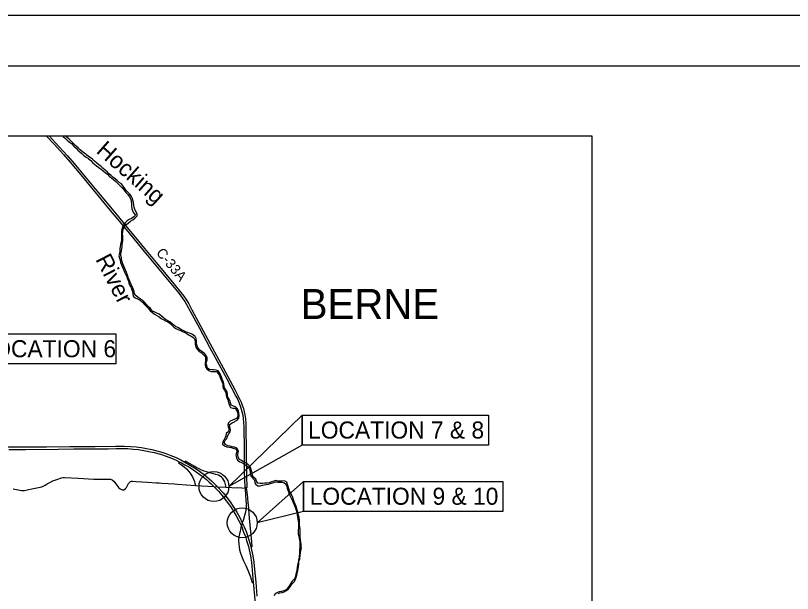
# Model space of a CAD drawing. Extents: x -51.9 to 34, y 0 to 23.3.
# Drawn here: x 6.91 to 14.66, y 16.24 to 22 of the extents above; entities that cross this region are included whole.
import ezdxf

# ---------------------------------------------------------------- set-up
doc = ezdxf.new("R2010")
doc.units = 0
for name, color, linetype in [('BR_P_Gen_Text', 7, 'Continuous'), ('Default', 7, 'Continuous'), ('GM_X_County_Road', 7, 'Continuous'), ('GM_X_County_Road_Text', 7, 'Continuous'), ('GM_X_Interchange_Ramps', 7, 'Continuous'), ('GM_X_Major_River', 7, 'Continuous'), ('GM_X_Major_River_Text', 7, 'Continuous'), ('GM_X_Township_Road', 7, 'Continuous'), ('GM_X_Township_Text', 7, 'Continuous'), ('GM_X_US_Route', 7, 'Continuous'), ('SH_Border', 7, 'Continuous'), ('SH_Cut_Line', 7, 'Continuous'), ('SH_Text', 7, 'Continuous')]:
    doc.layers.add(name, color=color, linetype=linetype)

msp = doc.modelspace()

# ---------------------------------------------------------------- linework, layer by layer
at = {"layer": 'BR_P_Gen_Text'}
for points in [[(6.5006, 18.827), (7.9094, 18.827), (7.9094, 18.5268), (6.5006, 18.5268)], [(9.7675, 18.0164), (9.7675, 17.7161), (9.0381, 17.3043)], [(9.7675, 18.0164), (11.6271, 18.0164), (11.6271, 17.7161), (9.7675, 17.7161)], [(9.7836, 17.3563), (9.7836, 17.056), (9.3204, 16.9434)], [(9.7836, 17.3563), (11.7711, 17.3563), (11.7711, 17.056), (9.7836, 17.056)]]:
    msp.add_lwpolyline(points, close=True, dxfattribs=at)
at = {"layer": 'Default'}
for centre in [(8.8891, 17.3043), (9.1714, 16.9434)]:
    msp.add_circle(centre, 0.149, dxfattribs=at)
at = {"layer": 'GM_X_County_Road'}
msp.add_line((9.2072, 17.2853), (9.1259, 17.2912), dxfattribs=at)
for points in [[(7.2165, 20.8014), (7.2937, 20.7181), (7.3887, 20.6148), (7.4551, 20.5389), (7.5602, 20.4136), (7.6838, 20.2636), (7.8384, 20.0776), (7.9796, 19.9067), (8.0908, 19.7728), (8.1642, 19.6842), (8.3391, 19.4732), (8.5374, 19.233), (8.5735, 19.1864), (8.5995, 19.1478), (8.6324, 19.0911), (8.7437, 18.8833), (8.8459, 18.6944), (8.9023, 18.5907), (9.0168, 18.378), (9.1078, 18.2071), (9.1262, 18.171), (9.141, 18.1359), (9.1548, 18.0984), (9.1688, 18.0528), (9.1764, 18.0146), (9.1819, 17.9788), (9.1851, 17.9474), (9.1869, 17.9004), (9.1894, 17.6782), (9.1909, 17.4499), (9.1967, 17.3), (9.2072, 17.2853)], [(7.2449, 20.8014), (7.3435, 20.6952), (7.4299, 20.601), (7.4952, 20.5238), (7.6044, 20.3929), (7.7527, 20.2143), (7.9056, 20.0299), (8.055, 19.8496), (8.1063, 19.7859), (8.1966, 19.6782), (8.3281, 19.5193), (8.4876, 19.3262), (8.5595, 19.2395), (8.5876, 19.204), (8.611, 19.169), (8.6373, 19.1259), (8.6691, 19.0673), (8.7584, 18.9008), (8.8526, 18.7271), (8.9162, 18.611), (9.0055, 18.4433), (9.0965, 18.2734), (9.1488, 18.1726), (9.1606, 18.146), (9.1716, 18.1148), (9.1829, 18.0812), (9.1907, 18.0492), (9.1971, 18.0211), (9.2028, 17.9781), (9.2069, 17.9333), (9.2083, 17.8659), (9.2115, 17.6888), (9.2124, 17.4033), (9.2173, 17.2984), (9.2072, 17.2853)], [(8.7051, 17.3164), (8.8891, 17.3043), (8.925, 17.3025), (9.0082, 17.2985), (9.1259, 17.2912)], [(8.7051, 17.3164), (8.8891, 17.3043), (8.925, 17.3025), (9.0082, 17.2985), (9.1259, 17.2912)]]:
    msp.add_lwpolyline(points, dxfattribs=at)
at = {"layer": 'GM_X_Interchange_Ramps'}
for points in [[(8.5419, 17.5519), (8.535, 17.5396), (8.5644, 17.5208), (8.591, 17.5003), (8.6162, 17.48), (8.6387, 17.4549), (8.6589, 17.4277), (8.6699, 17.4109)], [(9.0082, 17.2985), (9.0061, 17.3114), (8.9975, 17.3499), (8.9892, 17.3678), (8.9767, 17.3855), (8.9655, 17.397), (8.9516, 17.4086), (8.9351, 17.4187), (8.9091, 17.4262), (8.8374, 17.4453), (8.7928, 17.4586), (8.7639, 17.4693), (8.7408, 17.4797), (8.7194, 17.4925), (8.6916, 17.5092), (8.6057, 17.5564), (8.6001, 17.5491)], [(9.0082, 17.2985), (9.0061, 17.3114), (8.9975, 17.3499), (8.9892, 17.3678), (8.9767, 17.3855), (8.9655, 17.397), (8.9516, 17.4086), (8.9351, 17.4187), (8.9091, 17.4262), (8.8374, 17.4453), (8.7928, 17.4586), (8.7639, 17.4693), (8.7408, 17.4797), (8.7194, 17.4925), (8.6916, 17.5092), (8.6057, 17.5564), (8.6001, 17.5491)], [(8.6699, 17.4109), (8.6754, 17.4025), (8.6867, 17.3765), (8.6939, 17.356), (8.6986, 17.3357), (8.7051, 17.3164)], [(9.2072, 17.2853), (9.1989, 17.2752), (9.2083, 17.1733), (9.2109, 17.1288), (9.2095, 17.0923), (9.204, 17.0498), (9.1912, 17.0024), (9.1802, 16.9647), (9.1714, 16.9434), (9.1625, 16.9113), (9.1577, 16.895), (9.1502, 16.8569), (9.1438, 16.8341), (9.1383, 16.8032), (9.1357, 16.7676), (9.1372, 16.7309), (9.1395, 16.7034), (9.1444, 16.6736), (9.1537, 16.6404), (9.1629, 16.614), (9.1846, 16.5649), (9.2064, 16.5181), (9.2274, 16.4709), (9.2401, 16.4379), (9.2543, 16.4042), (9.2611, 16.3825), (9.2693, 16.3488), (9.282, 16.3528)], [(9.2326, 17.1263), (9.2318, 17.1354), (9.2266, 17.1949), (9.2156, 17.2765), (9.2072, 17.2853)], [(9.2572, 16.7055), (9.2711, 16.7068), (9.2636, 16.7895), (9.2537, 16.8873), (9.2451, 16.9885), (9.2326, 17.1263)]]:
    msp.add_lwpolyline(points, dxfattribs=at)
at = {"layer": 'GM_X_Major_River'}
for points in [[(7.3779, 20.8014), (7.3857, 20.7943), (7.407, 20.7744), (7.4243, 20.7584), (7.4476, 20.7385), (7.4669, 20.7239), (7.4922, 20.6993), (7.5149, 20.6787), (7.5329, 20.6581), (7.5515, 20.6422), (7.5728, 20.6236), (7.5908, 20.6063), (7.6154, 20.5877), (7.6367, 20.5738), (7.6387, 20.5704)], [(7.8369, 20.4254), (7.8258, 20.4371), (7.7805, 20.4782), (7.7632, 20.4935), (7.7399, 20.5114), (7.7212, 20.5274), (7.6986, 20.5473), (7.6773, 20.5679), (7.656, 20.5858), (7.6387, 20.5964), (7.618, 20.6124), (7.6007, 20.625), (7.5794, 20.6416), (7.5541, 20.6628), (7.5335, 20.6808), (7.5102, 20.7014), (7.4902, 20.722), (7.4682, 20.7446), (7.4449, 20.7692), (7.4209, 20.7877), (7.406, 20.8014)], [(7.6387, 20.5704), (7.6594, 20.5558), (7.6787, 20.5366), (7.7007, 20.516), (7.7173, 20.5014), (7.7399, 20.4854), (7.7626, 20.4675), (7.7846, 20.4509), (7.8079, 20.433), (7.8265, 20.4191), (7.8485, 20.3971), (7.8665, 20.3825), (7.8904, 20.3619), (7.9104, 20.346), (7.9337, 20.3234)], [(7.981, 19.8022), (7.9783, 19.8242), (7.9802, 19.8469), (7.9835, 19.8675), (7.9934, 19.8902), (8.0093, 19.913), (8.0325, 19.931), (8.057, 19.9491), (8.0802, 19.9645), (8.1047, 19.9819), (8.1226, 20.0027), (8.1245, 20.0213), (8.1118, 20.0433), (8.0998, 20.0659), (8.0938, 20.0892), (8.0911, 20.1112), (8.0883, 20.1346), (8.0816, 20.1579), (8.0776, 20.1745), (8.0656, 20.1965), (8.0522, 20.2151), (8.0336, 20.2351), (8.0143, 20.257), (7.9989, 20.2763), (7.9829, 20.2989), (7.9656, 20.3215), (7.9443, 20.3368), (7.9243, 20.3547), (7.903, 20.3733), (7.881, 20.3899), (7.8591, 20.4085), (7.8369, 20.4254)], [(7.9337, 20.3234), (7.9544, 20.3035), (7.9737, 20.2822), (7.991, 20.2609), (8.0117, 20.237), (8.0303, 20.2164), (8.047, 20.1938), (8.061, 20.1698), (8.0644, 20.1478), (8.0678, 20.1238), (8.0678, 20.0992), (8.0706, 20.0765), (8.0779, 20.0545), (8.09, 20.0312), (8.106, 20.01), (8.0901, 19.9926), (8.0669, 19.9758), (8.045, 19.9657), (8.0238, 19.9537), (8.0039, 19.9343), (7.988, 19.9116), (7.9781, 19.8909), (7.9695, 19.8675), (7.9676, 19.8508), (7.967, 19.8301), (7.9677, 19.8041), (7.9684, 19.7875), (7.9665, 19.7661), (7.9639, 19.7421), (7.9586, 19.7188), (7.9547, 19.6974), (7.9515, 19.6741), (7.9502, 19.6507), (7.9463, 19.6281), (7.9417, 19.6054), (7.9458, 19.5814), (7.9538, 19.5601), (7.9578, 19.5374), (7.9659, 19.5141), (7.9772, 19.4908), (7.9873, 19.4675), (7.9973, 19.4422), (8.0073, 19.4209), (8.0193, 19.3956), (8.0267, 19.375), (8.0354, 19.3517), (8.0401, 19.331), (8.0515, 19.3084), (8.0622, 19.2884), (8.0708, 19.2665), (8.0762, 19.2491), (8.0789, 19.2251), (8.0823, 19.2012), (8.103, 19.1859), (8.1262, 19.1766), (8.1535, 19.1621), (8.1748, 19.1435), (8.1941, 19.1235), (8.2148, 19.1009), (8.2348, 19.0797), (8.2541, 19.0571), (8.2754, 19.0411), (8.2967, 19.0239), (8.3193, 19.0093), (8.342, 18.9967), (8.3613, 18.9814), (8.3819, 18.9688), (8.4045, 18.9582), (8.4285, 18.9476), (8.4504, 18.9344), (8.4677, 18.9138), (8.4891, 18.8938), (8.5103, 18.8806), (8.533, 18.8713), (8.5549, 18.8614), (8.5769, 18.8508), (8.5981, 18.8389), (8.6214, 18.8256), (8.6421, 18.8143), (8.6627, 18.8037), (8.6893, 18.7878), (8.6987, 18.7659), (8.7034, 18.7445), (8.7028, 18.7199), (8.7101, 18.6952), (8.7202, 18.6739), (8.7415, 18.6513), (8.7634, 18.6367), (8.7848, 18.6188), (8.8034, 18.5962), (8.8061, 18.5755), (8.8042, 18.5575), (8.8023, 18.5355), (8.803, 18.5155), (8.8063, 18.4989), (8.817, 18.4769), (8.8383, 18.4603), (8.8603, 18.4517), (8.8829, 18.4498), (8.9028, 18.4512), (8.9148, 18.4512)], [(9.0928, 17.9512), (9.0995, 17.9558), (9.1214, 17.9659), (9.1386, 17.9846), (9.1392, 18.014), (9.1384, 18.038), (9.1331, 18.0566), (9.1237, 18.0799), (9.1057, 18.1005), (9.0831, 18.1051), (9.0618, 18.1157), (9.0531, 18.139), (9.0478, 18.1623), (9.0331, 18.1843), (9.0257, 18.2063), (9.025, 18.2249), (9.0216, 18.2483), (9.0063, 18.2695), (8.9949, 18.2902), (8.9896, 18.3081), (8.9862, 18.3301), (8.9821, 18.3521), (8.9708, 18.3748), (8.9667, 18.3921), (8.9587, 18.4107), (8.9487, 18.436), (8.9307, 18.4586), (8.9121, 18.4646), (8.8895, 18.4685), (8.8669, 18.4671), (8.8456, 18.4703), (8.825, 18.4863), (8.8176, 18.5109), (8.8129, 18.5289), (8.8135, 18.5462), (8.8201, 18.5689), (8.8227, 18.5896), (8.8127, 18.6102), (8.796, 18.6322), (8.7721, 18.6481), (8.7481, 18.6647), (8.7281, 18.6893), (8.7194, 18.7133), (8.716, 18.7359), (8.7159, 18.7586), (8.7126, 18.7792), (8.7012, 18.8005), (8.6766, 18.8198), (8.6546, 18.8297), (8.6314, 18.8376), (8.6094, 18.8462), (8.5881, 18.8562), (8.5668, 18.8667), (8.5469, 18.8787), (8.5296, 18.8886), (8.5063, 18.9005), (8.4717, 18.9258), (8.4484, 18.9464), (8.4271, 18.9583), (8.4045, 18.9715), (8.3832, 18.9888), (8.3639, 19.0061), (8.3412, 19.024), (8.3193, 19.0333), (8.3, 19.0419), (8.2774, 19.0545), (8.2554, 19.0784), (8.2327, 19.101), (8.2127, 19.1216), (8.1954, 19.1422), (8.1761, 19.1635), (8.1528, 19.1767), (8.1348, 19.188), (8.1149, 19.2053), (8.0969, 19.2272), (8.0948, 19.2505), (8.0828, 19.2752), (8.0721, 19.2985), (8.0641, 19.3178), (8.052, 19.3411), (8.0433, 19.367), (8.034, 19.3883), (8.0253, 19.4116), (8.0166, 19.4376), (8.0099, 19.4556), (8.0012, 19.4769), (7.9905, 19.5009), (7.9818, 19.5248), (7.9737, 19.5461), (7.9677, 19.5675), (7.9663, 19.5841), (7.9603, 19.6081), (7.9615, 19.6321), (7.9655, 19.6541), (7.9694, 19.6755), (7.972, 19.6975), (7.9733, 19.7142), (7.9779, 19.7375), (7.9791, 19.7542), (7.9811, 19.7795), (7.981, 19.8022)], [(8.9148, 18.4512), (8.9314, 18.4326), (8.9454, 18.4113), (8.9521, 18.39), (8.9575, 18.3734), (8.9682, 18.3514), (8.9762, 18.3301), (8.9776, 18.3061), (8.9823, 18.2835), (8.9963, 18.2608), (9.0077, 18.2402), (9.0117, 18.2196), (9.0158, 18.1969), (9.0285, 18.1736), (9.0325, 18.1563), (9.0392, 18.1323), (9.0446, 18.111), (9.0553, 18.091), (9.0759, 18.0858), (9.1004, 18.0852), (9.1131, 18.0646), (9.1225, 18.0413), (9.1259, 18.0219), (9.1259, 18.0039), (9.1187, 17.9872), (9.0988, 17.9752), (9.0749, 17.9664), (9.0517, 17.9564), (9.0318, 17.9356), (9.0265, 17.9189), (9.0299, 17.8983), (9.0393, 17.875), (9.0294, 17.8516), (9.0121, 17.8342), (9.0076, 17.8095), (9.0023, 17.7922), (8.9864, 17.7668), (8.9778, 17.7494), (8.9746, 17.7274), (8.9952, 17.7095), (9.0185, 17.7016), (9.0404, 17.6983), (9.0617, 17.6924), (9.0823, 17.6865), (9.1049, 17.6805), (9.1202, 17.6606), (9.113, 17.6392), (9.1084, 17.6165), (9.1131, 17.5912), (9.1245, 17.5686), (9.1464, 17.5507), (9.1637, 17.5434), (9.1877, 17.5301), (9.2316, 17.501), (9.2443, 17.4797), (9.2503, 17.4577), (9.2517, 17.4397), (9.2537, 17.423), (9.2571, 17.4064), (9.2931, 17.3665), (9.2985, 17.3432), (9.3058, 17.3252), (9.3265, 17.3126), (9.3497, 17.3127), (9.3729, 17.3188), (9.3915, 17.3215), (9.4115, 17.3242), (9.4314, 17.3283)], [(9.5489, 17.3567), (9.5276, 17.358), (9.5077, 17.3639), (9.4877, 17.3592), (9.4645, 17.3511), (9.4413, 17.343), (9.4181, 17.3383), (9.3961, 17.3382), (9.3729, 17.3348), (9.3497, 17.3334), (9.3264, 17.3366), (9.315, 17.3566), (9.3057, 17.3772), (9.2864, 17.3945), (9.2737, 17.4158), (9.269, 17.4411), (9.2649, 17.4611), (9.2582, 17.485), (9.2469, 17.5063), (9.2269, 17.5283), (9.2069, 17.5375), (9.1856, 17.5481), (9.163, 17.5627), (9.1424, 17.5753), (9.1297, 17.5973), (9.1277, 17.6199), (9.1309, 17.642), (9.1335, 17.6586), (9.1175, 17.687), (9.0949, 17.6958), (9.0723, 17.7018), (9.0504, 17.707), (9.0264, 17.7116), (9.0045, 17.7242), (8.9911, 17.7428), (9.0024, 17.7655), (9.0169, 17.7849), (9.0235, 17.8069), (9.0374, 17.8296), (9.0506, 17.8503), (9.0559, 17.8677), (9.0491, 17.901), (9.0458, 17.9223), (9.071, 17.9411), (9.0928, 17.9512)], [(9.5287, 16.2387), (9.5473, 16.2441), (9.5686, 16.2495), (9.5905, 16.2562), (9.613, 16.267), (9.6322, 16.2843), (9.6494, 16.3064), (9.6673, 16.3311), (9.6878, 16.3545), (9.7011, 16.3786), (9.7103, 16.4006), (9.7162, 16.4226), (9.7208, 16.4393), (9.7261, 16.464), (9.73, 16.4853), (9.7339, 16.508), (9.7352, 16.5293), (9.7371, 16.5534), (9.7407, 16.5684), (9.7454, 16.5842), (9.7482, 16.6187), (9.7535, 16.6421), (9.7574, 16.6634), (9.7613, 16.6888), (9.7606, 16.7061), (9.7592, 16.7294), (9.7571, 16.7507), (9.7538, 16.7727), (9.7497, 16.7954), (9.7483, 16.818), (9.7483, 16.838), (9.7482, 16.8774), (9.7468, 16.8994), (9.7434, 16.9234), (9.7433, 16.9474), (9.7419, 16.9707), (9.7379, 16.9973), (9.7331, 17.02), (9.7291, 17.038), (9.7237, 17.06), (9.7157, 17.0839), (9.7083, 17.1066), (9.7003, 17.1299), (9.6903, 17.1525), (9.6842, 17.1705), (9.6749, 17.1938), (9.6648, 17.2184), (9.6562, 17.2364), (9.6441, 17.259), (9.6348, 17.281), (9.6294, 17.3036), (9.6234, 17.3263), (9.6153, 17.3496), (9.5934, 17.3608), (9.5714, 17.3594), (9.5489, 17.3567)], [(9.4314, 17.3283), (9.4546, 17.3364), (9.4778, 17.3431), (9.5037, 17.3499), (9.527, 17.3479), (9.5496, 17.3467), (9.5675, 17.3468), (9.5854, 17.3441), (9.6054, 17.3275), (9.6174, 17.3063), (9.6208, 17.2883), (9.6275, 17.2683), (9.6329, 17.2516), (9.6376, 17.2337), (9.6503, 17.207), (9.6616, 17.1824), (9.6723, 17.1611), (9.683, 17.1365), (9.6924, 17.1145), (9.7024, 17.0905), (9.7084, 17.0692), (9.7145, 17.0453), (9.7185, 17.0239), (9.7266, 16.9786), (9.7293, 16.9606), (9.732, 16.94), (9.7328, 16.9153), (9.7322, 16.8933), (9.7296, 16.8713), (9.729, 16.8546), (9.7303, 16.8333), (9.7351, 16.8093), (9.7398, 16.7867), (9.7445, 16.7627), (9.7465, 16.74), (9.7466, 16.716), (9.7453, 16.6974), (9.7441, 16.6747), (9.7435, 16.654), (9.7422, 16.6314), (9.7403, 16.6134), (9.739, 16.5954), (9.7331, 16.5707), (9.7285, 16.5453), (9.7232, 16.5193), (9.72, 16.496), (9.7167, 16.4786), (9.7121, 16.4526), (9.7069, 16.4313), (9.701, 16.4092), (9.6911, 16.3859), (9.6699, 16.3598), (9.6533, 16.3357), (9.6414, 16.317), (9.6276, 16.2963), (9.6083, 16.2743), (9.5871, 16.2635), (9.5632, 16.2575), (9.5413, 16.2554), (9.5241, 16.2493), (9.5028, 16.2393), (9.4849, 16.2192)]]:
    msp.add_lwpolyline(points, dxfattribs=at)
at = {"layer": 'GM_X_Township_Road'}
for points in [[(6.8874, 17.2817), (6.9688, 17.2652), (6.9818, 17.2639), (6.9866, 17.2639), (6.9996, 17.2662), (7.0265, 17.2711), (7.0905, 17.2849), (7.1386, 17.2948), (7.1558, 17.2985), (7.1709, 17.3025), (7.1867, 17.3084), (7.2053, 17.3183), (7.2266, 17.3315), (7.2523, 17.3463), (7.2823, 17.3599), (7.3132, 17.3712), (7.3701, 17.3905), (7.3858, 17.3944), (7.3987, 17.3951), (7.534, 17.3875), (7.6897, 17.378), (7.8018, 17.3793), (7.8351, 17.3786), (7.8557, 17.3772), (7.8737, 17.3698), (7.8936, 17.3564), (7.9082, 17.3364), (7.9229, 17.3156), (7.9381, 17.2936), (7.9521, 17.2809), (7.972, 17.2722), (7.99, 17.2728), (8.0033, 17.2815), (8.0174, 17.2961), (8.0267, 17.3141), (8.0367, 17.3355), (8.0487, 17.3468), (8.0581, 17.3541), (8.0654, 17.3574), (8.0761, 17.3588), (8.112, 17.3553), (8.2258, 17.3485), (8.3159, 17.3421), (8.3423, 17.3402), (8.3697, 17.3386), (8.4962, 17.331)], [(8.4962, 17.331), (8.5261, 17.3292), (8.7051, 17.3164)]]:
    msp.add_lwpolyline(points, dxfattribs=at)
at = {"layer": 'GM_X_US_Route'}
for points in [[(5.8484, 17.6907), (6.8406, 17.6988), (7.2185, 17.702), (7.4511, 17.7035), (7.7038, 17.7053), (7.9057, 17.7069), (7.9978, 17.7074), (8.0617, 17.7046), (8.1123, 17.7004), (8.1664, 17.6937), (8.2167, 17.685), (8.2685, 17.6744), (8.3203, 17.661), (8.3709, 17.646), (8.409, 17.6339), (8.4588, 17.6153), (8.5109, 17.5934), (8.5591, 17.57), (8.6001, 17.5491)], [(6.8418, 17.6734), (7.0107, 17.6749), (7.3338, 17.6778), (7.49, 17.679), (7.6221, 17.6803), (7.7665, 17.6816), (7.8325, 17.6819), (7.9122, 17.6829), (7.9911, 17.6829), (8.03, 17.6824), (8.0831, 17.6785), (8.1362, 17.6736), (8.1881, 17.6651), (8.2397, 17.6555), (8.2915, 17.6437), (8.3559, 17.6259), (8.4121, 17.6071), (8.4663, 17.5867), (8.5117, 17.5664), (8.5419, 17.5519)], [(8.5419, 17.5519), (8.5667, 17.5393), (8.5982, 17.5222), (8.6387, 17.5), (8.6763, 17.4763), (8.7127, 17.4517), (8.7489, 17.4262), (8.7824, 17.4002), (8.8134, 17.3751), (8.8426, 17.3496), (8.8611, 17.3323), (8.8891, 17.3043)], [(8.6001, 17.5491), (8.6968, 17.4922), (8.7327, 17.4676), (8.7581, 17.4491), (8.7902, 17.4248), (8.8194, 17.4017), (8.8637, 17.3629), (8.912, 17.3163), (8.925, 17.3025), (8.9811, 17.2429), (9.0175, 17.1969), (9.0516, 17.1513), (9.0817, 17.107), (9.1178, 17.0486), (9.147, 16.9957), (9.1714, 16.9434), (9.1898, 16.9037), (9.2098, 16.856), (9.2384, 16.7742), (9.2572, 16.7055)], [(8.8891, 17.3043), (8.9354, 17.2574), (8.9692, 17.2178), (9.0025, 17.1767), (9.0348, 17.1328), (9.0612, 17.094), (9.0866, 17.0541), (9.1109, 17.0116), (9.1625, 16.9113), (9.1852, 16.8508), (9.2023, 16.8075), (9.2153, 16.7664), (9.2323, 16.7062), (9.2365, 16.6889)], [(9.2365, 16.6889), (9.2399, 16.675), (9.2532, 16.6137), (9.263, 16.5484), (9.268, 16.5101), (9.282, 16.3528)], [(9.2572, 16.7055), (9.2647, 16.6743), (9.278, 16.613), (9.2865, 16.5503), (9.294, 16.4769), (9.3056, 16.352), (9.3183, 16.2132)], [(9.282, 16.3528), (9.2946, 16.2117), (9.3015, 16.1264), (9.3105, 16.0434), (9.3172, 15.9992), (9.3319, 15.9324), (9.3507, 15.8723), (9.3519, 15.8691)]]:
    msp.add_lwpolyline(points, dxfattribs=at)
at = {"layer": 'SH_Border'}
msp.add_lwpolyline([(1.5, 21.5), (33.5, 21.5), (33.5, 0.5), (1.5, 0.5)], close=True, dxfattribs=at)
at = {"layer": 'SH_Cut_Line'}
msp.add_lwpolyline([(0, 0), (34, 0), (34, 22), (0, 22)], close=True, dxfattribs=at)
at = {"layer": 'SH_Text'}
msp.add_lwpolyline([(2.2024, 20.8014), (12.6582, 20.8014), (12.6582, 11.236), (2.2024, 11.236)], close=True, dxfattribs=at)

# ---------------------------------------------------------------- texts
at = {"layer": 'BR_P_Gen_Text'}
for s, p in [('LOCATION 6', (6.5614, 18.5936)), ('LOCATION 7 & 8', (9.8283, 17.783)), ('LOCATION 9 & 10', (9.8444, 17.1229))]:
    msp.add_text(s, height=0.17, dxfattribs=at).set_placement(p)
at = {"layer": 'GM_X_County_Road_Text'}
msp.add_text('C-33A', height=0.09988, rotation=309.64439, dxfattribs=at).set_placement((8.3068, 19.6324))
at = {"layer": 'GM_X_Major_River_Text'}
for s, height, rotation, p in [('Hocking', 0.16647, 318.64988, (7.7058, 20.6395)), ('River', 0.16645, 297.15229, (7.7035, 19.5702))]:
    msp.add_text(s, height=height, rotation=rotation, dxfattribs=at).set_placement(p)
at = {"layer": 'GM_X_Township_Text'}
msp.add_text('BERNE', height=0.29963, rotation=0.00001, dxfattribs=at).set_placement((9.7548, 18.9745))

doc.saveas('drawing.dxf')
